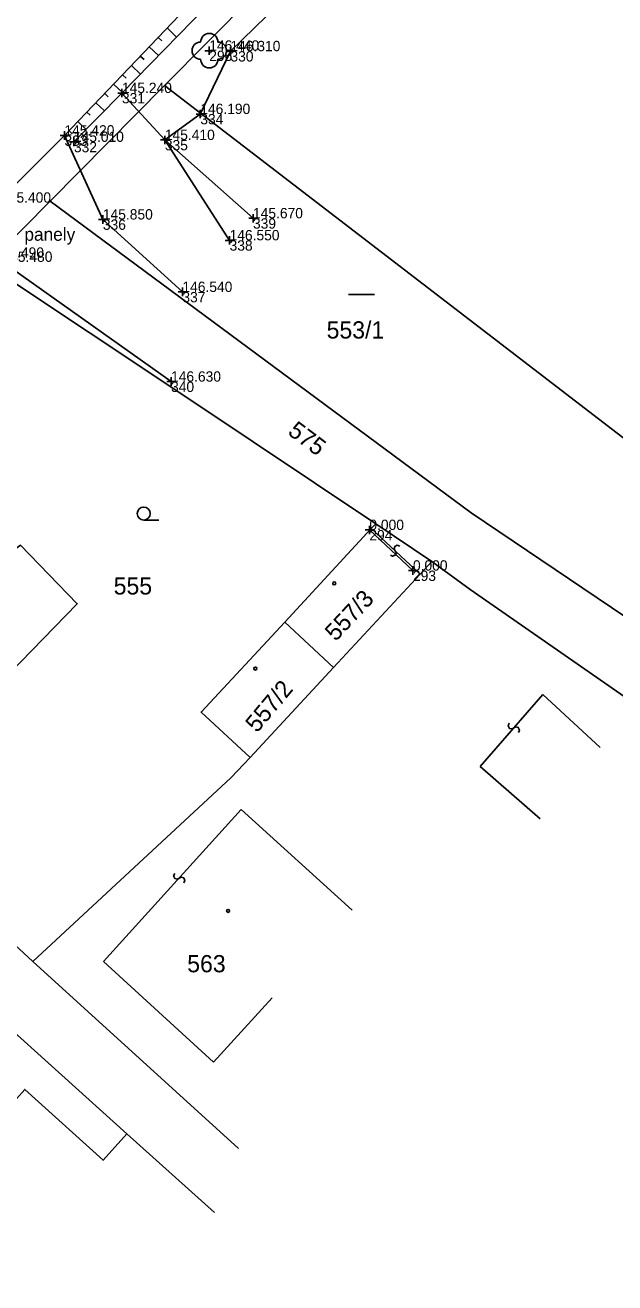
# Model space of a CAD drawing. Extents: x -748509 to -748117, y -967868 to -967533.
# Drawn here: x -748388.8 to -748354.6, y -967816.8 to -967743.8 of the extents above; entities that cross this region are included whole.
import ezdxf

# ---------------------------------------------------------------- set-up
doc = ezdxf.new("R2010")
doc.units = 0
for name, color, linetype in [('Body polohopisu', 7, 'Continuous'), ('Budovy', 7, 'Continuous'), ('KM', 7, 'Continuous'), ('Ploty_opěrné zdi', 7, 'Continuous'), ('Popisy objektů_povrchů', 7, 'Continuous'), ('Rozhraní ploch', 7, 'Continuous'), ('Stromy_porost', 7, 'Continuous'), ('Vnitřní kresba', 7, 'Continuous'), ('Výškopis', 7, 'Continuous'), ('Výšky bodů', 7, 'Continuous'), ('Čísla bodů', 7, 'Continuous')]:
    doc.layers.add(name, color=color, linetype=linetype)

msp = doc.modelspace()

# ---------------------------------------------------------------- linework, layer by layer
at = {"layer": 'Body polohopisu'}
for p, q in [((-748378.14, -967745.24), (-748378.39, -967745.24)), ((-748378.14, -967745.24), (-748378.14, -967744.99)), ((-748378.14, -967745.24), (-748377.89, -967745.24)), ((-748378.14, -967745.24), (-748378.14, -967745.49)), ((-748376.91, -967745.27), (-748377.16, -967745.27)), ((-748376.91, -967745.27), (-748376.91, -967745.02)), ((-748376.91, -967745.27), (-748376.66, -967745.27)), ((-748376.91, -967745.27), (-748376.91, -967745.52)), ((-748383.21, -967747.7), (-748383.46, -967747.7)), ((-748383.21, -967747.7), (-748383.21, -967747.45)), ((-748383.21, -967747.7), (-748382.96, -967747.7)), ((-748383.21, -967747.7), (-748383.21, -967747.95)), ((-748378.66, -967748.92), (-748378.91, -967748.92)), ((-748378.66, -967748.92), (-748378.66, -967748.67)), ((-748378.66, -967748.92), (-748378.41, -967748.92)), ((-748378.66, -967748.92), (-748378.66, -967749.17)), ((-748386.55, -967750.17), (-748386.55, -967749.92)), ((-748386.55, -967750.17), (-748386.8, -967750.17)), ((-748386.55, -967750.17), (-748386.3, -967750.17)), ((-748386.55, -967750.17), (-748386.55, -967750.42)), ((-748386, -967750.54), (-748386.25, -967750.54)), ((-748386, -967750.54), (-748386, -967750.29)), ((-748386, -967750.54), (-748385.75, -967750.54)), ((-748386, -967750.54), (-748386, -967750.79)), ((-748380.72, -967750.43), (-748380.97, -967750.43)), ((-748380.72, -967750.43), (-748380.72, -967750.18)), ((-748380.72, -967750.43), (-748380.47, -967750.43)), ((-748380.72, -967750.43), (-748380.72, -967750.68)), ((-748384.32, -967755.05), (-748384.57, -967755.05)), ((-748384.32, -967755.05), (-748384.32, -967754.8)), ((-748384.32, -967755.05), (-748384.07, -967755.05)), ((-748384.32, -967755.05), (-748384.32, -967755.3)), ((-748375.6, -967754.98), (-748375.85, -967754.98)), ((-748375.6, -967754.98), (-748375.6, -967754.73)), ((-748375.6, -967754.98), (-748375.35, -967754.98)), ((-748375.6, -967754.98), (-748375.6, -967755.23)), ((-748376.96, -967756.26), (-748377.21, -967756.26)), ((-748376.96, -967756.26), (-748376.96, -967756.01)), ((-748376.96, -967756.26), (-748376.71, -967756.26)), ((-748376.96, -967756.26), (-748376.96, -967756.51)), ((-748379.7, -967759.26), (-748379.95, -967759.26)), ((-748379.7, -967759.26), (-748379.7, -967759.01)), ((-748379.7, -967759.26), (-748379.45, -967759.26)), ((-748379.7, -967759.26), (-748379.7, -967759.51)), ((-748380.36, -967764.47), (-748380.61, -967764.47)), ((-748380.36, -967764.47), (-748380.36, -967764.22)), ((-748380.36, -967764.47), (-748380.11, -967764.47)), ((-748380.36, -967764.47), (-748380.36, -967764.72)), ((-748368.84, -967773.09), (-748369.09, -967773.09)), ((-748368.84, -967773.09), (-748368.84, -967772.84)), ((-748368.84, -967773.09), (-748368.59, -967773.09)), ((-748368.84, -967773.09), (-748368.84, -967773.34)), ((-748366.31, -967775.45), (-748366.56, -967775.45)), ((-748366.31, -967775.45), (-748366.31, -967775.2)), ((-748366.31, -967775.45), (-748366.06, -967775.45)), ((-748366.31, -967775.45), (-748366.31, -967775.7))]:
    msp.add_line(p, q, dxfattribs=at)
at = {"layer": 'Budovy'}
msp.add_lwpolyline([(-748366.31, -967775.45), (-748368.84, -967773.09)], dxfattribs=at)
at = {"layer": 'KM'}
for p, q in [((-748380.74, -967747.27), (-748354.82, -967721.07)), ((-748387.38, -967753.98), (-748380.74, -967747.27)), ((-748353.11, -967768.5), (-748380.74, -967747.27)), ((-748391.04, -967757.68), (-748387.38, -967753.98)), ((-748370.051, -967759.406), (-748368.551, -967759.406)), ((-748381.946, -967772.51), (-748381.071, -967772.51)), ((-748365.21, -967774.92), (-748368.47, -967772.73)), ((-748370.92, -967781.08), (-748373.76, -967778.44)), ((-748375.77, -967786.31), (-748370.92, -967781.08)), ((-748397.69, -967789.61), (-748388.38, -967798.17)), ((-748388.38, -967798.17), (-748376.44, -967809.02)), ((-748382.92, -967808.17), (-748392.05, -967799.96)), ((-748377.83, -967812.75), (-748382.92, -967808.17))]:
    msp.add_line(p, q, dxfattribs=at)
for points in [[(-748387.38, -967753.98), (-748362.93, -967772.1), (-748350.73, -967780.33)], [(-748368.47, -967772.73), (-748379.15, -967765.58), (-748391.04, -967757.68)], [(-748397.69, -967789.61), (-748385.81, -967777.38), (-748389.1, -967773.98), (-748391.06, -967775.35), (-748397.83, -967768.66), (-748400.96, -967771.79), (-748401.41, -967771.4), (-748403.94, -967773.95), (-748403.545, -967774.342), (-748406.83, -967777.6), (-748409.975, -967774.486)], [(-748373.76, -967778.44), (-748368.73, -967773.01), (-748368.47, -967772.73)], [(-748370.92, -967781.08), (-748365.89, -967775.65), (-748365.21, -967774.92)], [(-748353.35, -967783.24), (-748362.99, -967776.55), (-748365.21, -967774.92)], [(-748375.77, -967786.31), (-748378.62, -967783.67), (-748373.76, -967778.44)], [(-748388.38, -967798.17), (-748376.88, -967787.5), (-748375.77, -967786.31)], [(-748382.92, -967808.17), (-748384.31, -967809.71), (-748388.86, -967805.6), (-748390.33, -967807.23), (-748392.04, -967805.66), (-748393.08, -967806.79), (-748393.4, -967806.5), (-748396.23, -967809.74), (-748394.19, -967811.48), (-748396.14, -967813.63), (-748389.22, -967819.88), (-748386.98, -967821.91)]]:
    msp.add_lwpolyline(points, dxfattribs=at)
for centre, radius in [((-748381.946, -967772.135), 0.375), ((-748370.883, -967776.19), 0.0875), ((-748375.463, -967781.14), 0.0875), ((-748377.043, -967795.22), 0.0875)]:
    msp.add_circle(centre, radius, dxfattribs=at)
at = {"layer": 'Ploty_opěrné zdi'}
for points in [[(-748378.66, -967748.92), (-748376.91, -967745.27), (-748368.58, -967737.15), (-748341.64, -967709.04), (-748325.07, -967691.76), (-748317.91, -967693.18), (-748310.76, -967696.83)], [(-748380.36, -967764.47), (-748390.15, -967757.51), (-748392.77, -967757.21), (-748412.07, -967776.59), (-748407.97, -967780.3)]]:
    msp.add_lwpolyline(points, dxfattribs=at)
at = {"layer": 'Rozhraní ploch'}
for points in [[(-748379.7, -967759.26), (-748384.32, -967755.05), (-748386.55, -967750.17), (-748369.03, -967731.8), (-748343.77, -967705.84), (-748327.45, -967688.79), (-748321.7, -967685.59), (-748315.42, -967685.01), (-748308.7, -967689.33)], [(-748393.1, -967756.68), (-748386.55, -967750.17)]]:
    msp.add_lwpolyline(points, dxfattribs=at)
at = {"layer": 'Stromy_porost'}
msp.add_lwpolyline([(-748378.66, -967748.92), (-748380.72, -967750.43), (-748376.96, -967756.26)], dxfattribs=at)
msp.add_circle((-748378.14, -967745.24), 0.0005, dxfattribs=at)
for centre, start, end in [((-748378.64, -967745.24), 89.99999, 269.99999), ((-748378.14, -967744.74), 0, 179.99999), ((-748377.64, -967745.24), 270, 89.99999), ((-748378.14, -967745.74), 179.99999, 359.99999)]:
    msp.add_arc(centre, 0.5, start, end, dxfattribs=at)
at = {"layer": 'Vnitřní kresba'}
for p, q in [((-748365.89, -967775.65), (-748368.73, -967773.01)), ((-748362.41, -967786.84), (-748358.77, -967782.65)), ((-748358.77, -967782.65), (-748355.44, -967785.72)), ((-748358.92, -967789.88), (-748362.41, -967786.84)), ((-748384.28, -967798.16), (-748376.28, -967789.34)), ((-748376.28, -967789.34), (-748369.85, -967795.18)), ((-748377.89, -967804.01), (-748384.28, -967798.16)), ((-748374.49, -967800.28), (-748377.89, -967804.01))]:
    msp.add_line(p, q, dxfattribs=at)
for points in [[(-748367.075, -967774.036), (-748367.219, -967773.971), (-748367.369, -967774.044), (-748367.409, -967774.19), (-748367.291, -967774.416), (-748367.343, -967774.559), (-748367.493, -967774.618), (-748367.623, -967774.552)], [(-748360.722, -967784.324), (-748360.782, -967784.47), (-748360.705, -967784.617), (-748360.557, -967784.653), (-748360.335, -967784.527), (-748360.19, -967784.574), (-748360.127, -967784.722), (-748360.188, -967784.854)], [(-748380.146, -967793.045), (-748380.21, -967793.189), (-748380.135, -967793.338), (-748379.988, -967793.377), (-748379.764, -967793.256), (-748379.62, -967793.306), (-748379.56, -967793.455), (-748379.624, -967793.585)]]:
    msp.add_lwpolyline(points, dxfattribs=at)
at = {"layer": 'Výškopis'}
for points in [[(-748310.26, -967693.3), (-748319.69, -967689.71), (-748326.66, -967689.92), (-748343.09, -967706.41), (-748368.35, -967732.47), (-748383.21, -967747.7), (-748386, -967750.54)], [(-748380.591, -967743.922), (-748380.038, -967744.449)], [(-748381.109, -967744.465), (-748380.89, -967744.673)], [(-748382.144, -967745.55), (-748381.93, -967745.754)], [(-748381.626, -967745.007), (-748381.086, -967745.523)], [(-748382.662, -967746.093), (-748382.133, -967746.597)], [(-748383.179, -967746.636), (-748382.97, -967746.835)], [(-748384.214, -967747.721), (-748384.011, -967747.915)], [(-748383.697, -967747.178), (-748383.181, -967747.67)], [(-748383.21, -967747.7), (-748380.72, -967750.43), (-748375.6, -967754.98)], [(-748384.732, -967748.264), (-748384.232, -967748.74)], [(-748385.25, -967748.807), (-748385.053, -967748.994)], [(-748386.285, -967749.892), (-748386.095, -967750.074)], [(-748385.767, -967749.349), (-748385.283, -967749.811)]]:
    msp.add_lwpolyline(points, dxfattribs=at)

# ---------------------------------------------------------------- texts
at = {"layer": 'KM'}
for s, p in [('553/1', (-748371.324, -967761.965)), ('555', (-748383.692, -967776.84)), ('563', (-748379.42, -967798.79))]:
    msp.add_text(s, height=1, dxfattribs=at).set_placement(p)
for s, rotation, p in [('575', 323, (-748373.637, -967767.493)), ('557/3', 47, (-748370.793, -967779.604)), ('557/2', 50, (-748375.367, -967784.919))]:
    msp.add_text(s, height=1, rotation=rotation, dxfattribs=at).set_placement(p)
at = {"layer": 'Popisy objektů_povrchů'}
msp.add_text('panely', height=0.75, dxfattribs=at).set_placement((-748388.878, -967756.284))
at = {"layer": 'Výšky bodů'}
for s, p in [('146.440', (-748378.14, -967745.24)), ('146.310', (-748376.91, -967745.27)), ('145.240', (-748383.21, -967747.7)), ('146.190', (-748378.66, -967748.92)), ('145.420', (-748386.55, -967750.17)), ('145.010', (-748386, -967750.54)), ('145.410', (-748380.72, -967750.43)), ('145.400', (-748390.23, -967754.07)), ('145.670', (-748375.6, -967754.98)), ('145.850', (-748384.32, -967755.05)), ('146.550', (-748376.96, -967756.26)), ('145.490', (-748390.64, -967757.27)), ('145.480', (-748390.15, -967757.51)), ('146.540', (-748379.7, -967759.26)), ('146.630', (-748380.36, -967764.47)), ('0.000', (-748368.84, -967773.09)), ('0.000', (-748366.31, -967775.45))]:
    msp.add_text(s, height=0.6, dxfattribs=at).set_placement(p)
at = {"layer": 'Čísla bodů'}
for s, p in [('296', (-748378.14, -967745.84)), ('330', (-748376.91, -967745.87)), ('331', (-748383.21, -967748.3)), ('334', (-748378.66, -967749.52)), ('333', (-748386.55, -967750.77)), ('332', (-748386, -967751.14)), ('335', (-748380.72, -967751.03)), ('336', (-748384.32, -967755.65)), ('339', (-748375.6, -967755.58)), ('338', (-748376.96, -967756.86)), ('337', (-748379.7, -967759.86)), ('340', (-748380.36, -967765.07)), ('294', (-748368.84, -967773.69)), ('293', (-748366.31, -967776.05))]:
    msp.add_text(s, height=0.6, dxfattribs=at).set_placement(p)

doc.saveas('drawing.dxf')
